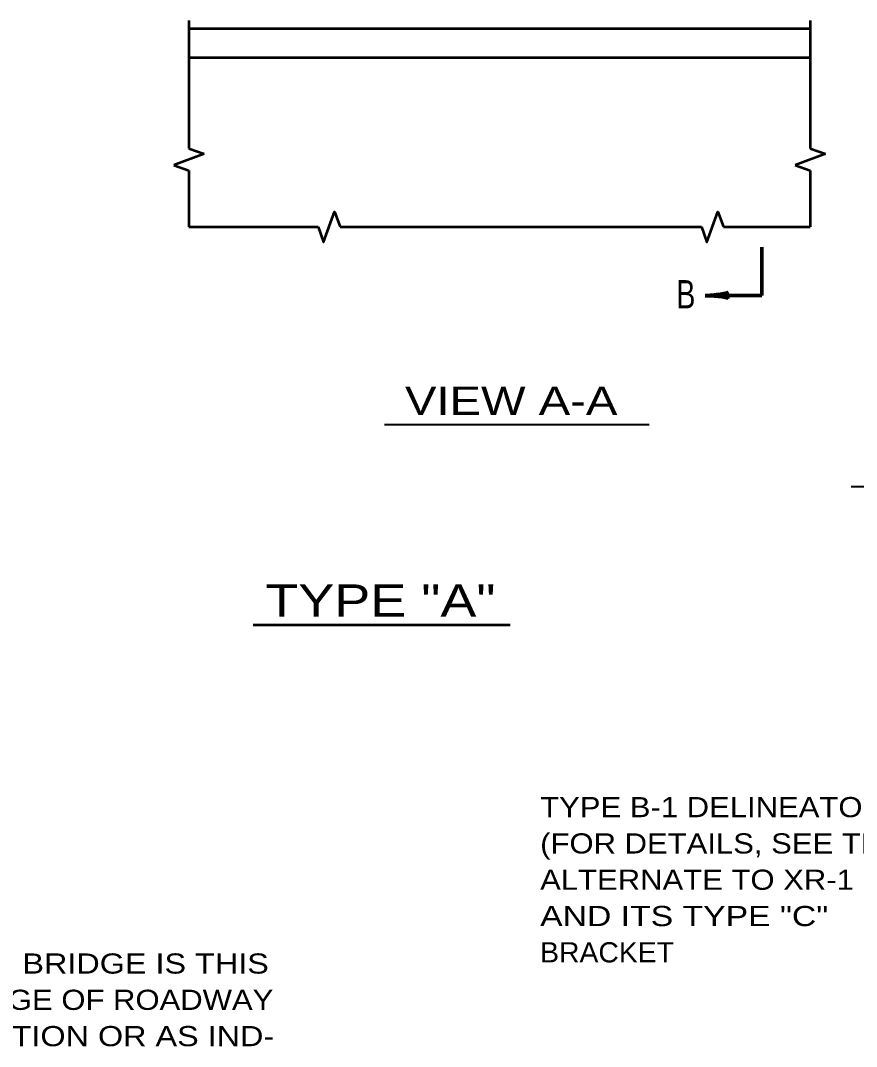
# Model space of a CAD drawing. Extents: x -105 to 751, y -65 to 479.
# Drawn here: x 183.9 to 308.2, y 212.5 to 365.2 of the extents above; entities that cross this region are included whole.
import ezdxf

# ---------------------------------------------------------------- set-up
doc = ezdxf.new("R2010")
doc.units = 0
doc.header["$LTSCALE"] = 1.2
doc.layers.add('1', color=7, linetype='Continuous', lineweight=35)

msp = doc.modelspace()

# ---------------------------------------------------------------- linework, layer by layer
at = {"layer": '1', "lineweight": 53}
for p, q in [((208.947, 365.162), (208.947, 346.129)), ((301.347, 365.162), (301.347, 346.129)), ((208.947, 363.962), (301.347, 363.962)), ((208.947, 359.646), (301.347, 359.646)), ((211.202, 345.308), (206.692, 343.667)), ((208.947, 346.129), (211.202, 345.308)), ((303.602, 345.308), (299.091, 343.667)), ((301.347, 346.129), (303.602, 345.308)), ((206.692, 343.667), (208.947, 342.846)), ((299.091, 343.667), (301.347, 342.846)), ((208.947, 342.846), (208.947, 334.446)), ((301.347, 342.846), (301.347, 334.446)), ((208.947, 334.446), (228.147, 334.446)), ((231.43, 334.446), (285.147, 334.446)), ((288.43, 334.446), (301.347, 334.446)), ((218.475, 275.258), (256.697, 275.258))]:
    msp.add_line(p, q, dxfattribs=at)
at = {"layer": '1', "lineweight": 70}
for q in [(294.147, 331.446), (285.747, 324.246)]:
    msp.add_line((294.147, 324.246), q, dxfattribs=at)
at = {"layer": '1', "lineweight": 40}
for p, q in [((237.999, 305.088), (277.409, 305.088)), ((307.442, 295.838), (431.709, 295.838))]:
    msp.add_line(p, q, dxfattribs=at)
at = {"layer": '1', "lineweight": 53}
for points in [[(228.147, 334.446), (228.968, 332.191), (230.609, 336.701), (231.43, 334.446)], [(285.147, 334.446), (285.968, 332.191), (287.609, 336.701), (288.43, 334.446)]]:
    msp.add_lwpolyline(points, dxfattribs=at)
at = {"layer": '1', "lineweight": 70}
for centre, major_axis, ratio, start_param, end_param in [((287.078, 324.504), (-2.105, -0.233), 0.07063, 0.8650754, 3.1424706), ((287.049, 323.918), (-2.145, 0.165), 0.122415, 3.1415927, 5.386832)]:
    msp.add_ellipse(centre, major_axis=major_axis, ratio=ratio, start_param=start_param, end_param=end_param, dxfattribs=at)

# ---------------------------------------------------------------- texts
at = {"layer": '1'}
for s, height, width, p in [('B', 4.2, 0.75, (281.445, 322.344)), ('VIEW A-A', 4.2, 1.25, (241.066, 306.494)), ('TYPE "A"', 4.8, 1.25, (220.304, 276.478)), ('TYPE B-1 DELINEATOR', 3, 1.15, (261.174, 246.643)), ('(FOR DETAILS, SEE TE11-5)', 3, 1.15, (261.174, 241.243)), ('ALTERNATE TO XR-1', 3, 1.15, (261.174, 235.843)), ('AND ITS TYPE "C"', 3, 1.25, (261.174, 230.443)), ('BRACKET', 3, 1.05, (261.174, 225.043)), ('EDGE OF ROADWAY ON BRIDGE IS THIS', 3, 1.2, (126.397, 223.377)), ('PROJECTION OF THE EDGE OF ROADWAY', 3, 1.15, (126.397, 217.977)), ('ON ADJACENT FILL SECTION OR AS IND-', 3, 1.2, (126.397, 212.577))]:
    msp.add_text(s, height=height, dxfattribs=dict(at, width=width)).set_placement(p)

doc.saveas('drawing.dxf')
